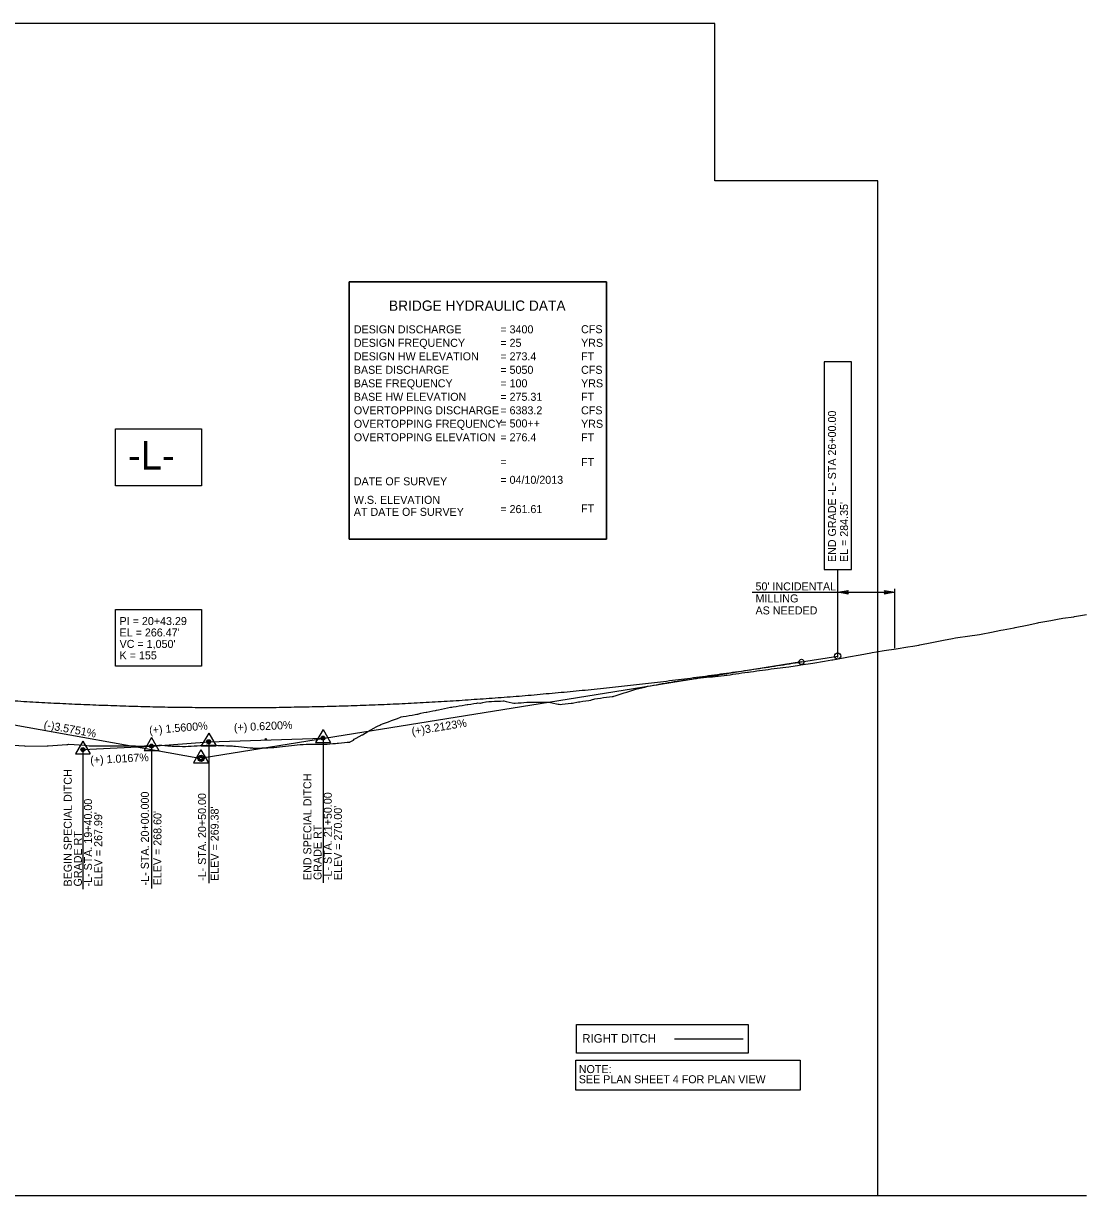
# Model space of a CAD drawing. Extents: x 10000 to 11818, y 10000 to 11025.
# Drawn here: x 10888 to 11818, y 10000 to 11025 of the extents above; entities that cross this region are included whole.
import ezdxf

# ---------------------------------------------------------------- set-up
doc = ezdxf.new("R2010")
doc.units = 0
for name, color, linetype in [('Exist Profile Cell', 7, 'Continuous'), ('Exist Vertical Profile Ground Line', 7, 'Continuous'), ('Prop Dimension', 7, 'Continuous'), ('Prop Grid Mask', 7, 'Continuous'), ('Prop PFL Ditch Label CELL', 7, 'Continuous'), ('Prop PFL VPI Symbol CELL', 7, 'Continuous'), ('Prop Plan Preparation Sheet Bridge Report Limited Study CELL', 7, 'Continuous'), ('Prop Terminator CELL', 7, 'Continuous'), ('Prop Vertical Profile Curve Label', 7, 'Continuous'), ('Prop Vertical Profile Ditch Grade Right', 7, 'Continuous'), ('Prop Vertical Profile Grade', 7, 'Continuous'), ('Prop Vertical Profile Grade Label', 7, 'Continuous'), ('Prop VPI Label', 7, 'Continuous'), ('Sheet Layout Profile Border', 7, 'Continuous'), ('Sheet Plot Border Outside CELL', 7, 'Continuous')]:
    doc.layers.add(name, color=color, linetype=linetype)

msp = doc.modelspace()

# ---------------------------------------------------------------- linework, layer by layer
at = {"layer": 'Exist Profile Cell'}
msp.add_line((10000, 10000), (11817.5, 10000), dxfattribs=at)
at = {"layer": 'Exist Vertical Profile Ground Line'}
msp.add_lwpolyline([(10869.3, 10394.5), (10889, 10393.2), (10889.9, 10393.1), (10908.7, 10393.2), (10909.6, 10393.2), (10926.1, 10394.3), (10926.5, 10394.4), (10926.9, 10394.5), (10927.6, 10394.8), (10941.4, 10393.9), (10945.4, 10393.2), (10967.1, 10393.4), (10968.6, 10393.4), (10970.5, 10393.4), (10978.2, 10393.3), (10980.8, 10393.2), (10983.3, 10393.2), (10985.9, 10393.2), (10988.8, 10393.1), (10991.1, 10393.1), (10993.8, 10393.2), (10996.2, 10393.3), (10998.8, 10393.4), (11001.4, 10393.5), (11003.9, 10393.6), (11006.5, 10393.8), (11009.1, 10393.9), (11011.7, 10393.6), (11014.2, 10393.4), (11016.8, 10393.2), (11018, 10393.1), (11019.4, 10393), (11022, 10393), (11024.5, 10392.9), (11027.1, 10392.8), (11029.3, 10392.7), (11029.7, 10392.7), (11032.2, 10392.9), (11034.8, 10393), (11037.4, 10393.2), (11040, 10393.3), (11042.5, 10393.5), (11043.2, 10393.5), (11045.1, 10393.6), (11047.7, 10393.8), (11049.7, 10393.9), (11050.3, 10393.9), (11052.8, 10393.9), (11053.9, 10393.9), (11055.4, 10393.8), (11058, 10393.7), (11060.6, 10393.6), (11063.1, 10393.5), (11065.7, 10393.4), (11068.3, 10393.3), (11070.5, 10393.2), (11070.9, 10393.2), (11072.1, 10393), (11073.4, 10392.9), (11076, 10392.6), (11078.6, 10392.4), (11081.1, 10392.1), (11083.7, 10391.8), (11086.3, 10391.6), (11088.3, 10391.4), (11088.9, 10391.3), (11090.6, 10391.1), (11091.4, 10391.2), (11092.6, 10391.3), (11094, 10391.3), (11096.6, 10391.4), (11099.2, 10391.5), (11101.7, 10391.6), (11104.3, 10391.7), (11105.4, 10391.8), (11106.9, 10391.9), (11109.5, 10392.1), (11111.7, 10392.3), (11112, 10392.3), (11114.6, 10392.6), (11117.2, 10392.9), (11119.8, 10393.2), (11122.3, 10393.5), (11124.9, 10393.8), (11127.5, 10394.1), (11130, 10394.3), (11132.6, 10394.5), (11135.2, 10394.6), (11137.8, 10394.6), (11140.3, 10394.7), (11142.9, 10394.7), (11143.8, 10394.8), (11145.5, 10394.7), (11148.1, 10394.7), (11150.6, 10394.7), (11153.2, 10394.7), (11153.7, 10394.7), (11155.8, 10394.9), (11158.4, 10395.2), (11160.9, 10395.4), (11162.2, 10395.5), (11163.5, 10395.7), (11166.1, 10395.9), (11168.7, 10396.2), (11171.2, 10396.4), (11173.3, 10396.6), (11173.8, 10396.9), (11176.6, 10398.3), (11177.2, 10399), (11178.9, 10400), (11181.5, 10401.4), (11184.1, 10402.8), (11184.5, 10403), (11186.7, 10404.3), (11189.2, 10405.7), (11191.8, 10407.2), (11194.4, 10408.6), (11196.5, 10409.8), (11197, 10410.1), (11197.6, 10410.5), (11199.5, 10411.4), (11200.6, 10411.8), (11202.1, 10412.4), (11204.7, 10413.4), (11207.3, 10414.4), (11209.8, 10415.4), (11212.4, 10416.3), (11215, 10417.3), (11217.6, 10418.3), (11218.2, 10418.6), (11220.1, 10418.9), (11222.7, 10419.3), (11225.3, 10419.8), (11227.8, 10420.2), (11230.4, 10420.7), (11232.1, 10420.9), (11233, 10421.1), (11235.6, 10421.7), (11238.1, 10422.3), (11240.2, 10422.7), (11240.7, 10422.8), (11243.3, 10423.3), (11245.9, 10423.8), (11248.4, 10424.3), (11249.3, 10424.5), (11251, 10424.8), (11253.6, 10425.4), (11256.2, 10425.9), (11258.7, 10426.4), (11261.3, 10427), (11262.5, 10427.2), (11263.9, 10427.4), (11266.5, 10427.8), (11269, 10428.2), (11271.6, 10428.6), (11274.2, 10429), (11276.1, 10429.3), (11276.7, 10429.4), (11279.3, 10429.8), (11281.9, 10430.3), (11284.5, 10430.7), (11285.1, 10430.8), (11287, 10430.7), (11287.7, 10430.7), (11289.6, 10431.1), (11292.2, 10431.7), (11292.7, 10431.9), (11294.8, 10432), (11297.3, 10432.1), (11299.9, 10432.2), (11302.5, 10432.3), (11305.1, 10432.4), (11307.6, 10432.5), (11308, 10432.5), (11310.2, 10432), (11312.8, 10431.5), (11315.4, 10430.9), (11316.7, 10430.6), (11317.9, 10430.7), (11320.5, 10430.9), (11323.1, 10431), (11325.6, 10431.2), (11328.2, 10431.4), (11331.1, 10431.6), (11331.4, 10431.6), (11332.4, 10431.6), (11333.4, 10431.6), (11335.9, 10431.6), (11338.5, 10431.6), (11341.1, 10431.5), (11343.7, 10431.5), (11346.2, 10431.5), (11346.8, 10431.5), (11348.8, 10431.1), (11351.4, 10430.6), (11354, 10430.1), (11355.7, 10429.8), (11356.5, 10429.7), (11357.9, 10429.4), (11359.1, 10429.6), (11361.7, 10429.9), (11364.3, 10430.2), (11366.8, 10430.5), (11368, 10430.7), (11369.4, 10430.9), (11372, 10431.4), (11373.3, 10431.7), (11374.5, 10431.8), (11377.1, 10432.2), (11379.7, 10432.5), (11382.3, 10432.8), (11384, 10433.1), (11384.8, 10433.4), (11387.7, 10434.4), (11390, 10434.7), (11392.6, 10435.1), (11395.1, 10435.4), (11397.7, 10435.7), (11400.3, 10436), (11402.9, 10436.3), (11403.6, 10436.4), (11404.3, 10436.6), (11405.4, 10437), (11408, 10437.9), (11410.6, 10438.7), (11413.2, 10439.5), (11415.7, 10440.3), (11418.3, 10441.1), (11420.9, 10441.9), (11423.4, 10442.8), (11426.1, 10443.5), (11428.6, 10444), (11430, 10444.2), (11431.2, 10444.6), (11433.2, 10445.3), (11433.7, 10445.4), (11436.3, 10445.8), (11438.9, 10446.2), (11441.5, 10446.6), (11442.1, 10446.7), (11444, 10447.2), (11446.5, 10447.8), (11449.2, 10448.2), (11451.8, 10448.6), (11454.3, 10449), (11456.9, 10449.4), (11459.5, 10449.8), (11461.2, 10450), (11462.1, 10450.2), (11464.6, 10450.6), (11467.2, 10450.9), (11469.8, 10451.3), (11472.3, 10451.7), (11474.9, 10452.1), (11476.6, 10452.3), (11477.5, 10452.4), (11480.1, 10452.7), (11482.6, 10453), (11485.2, 10453.2), (11487.8, 10453.5), (11490.4, 10453.7), (11492.9, 10454), (11494.1, 10454.1), (11495.5, 10454.3), (11498.1, 10454.6), (11500.7, 10454.8), (11502.2, 10455), (11503.2, 10455.2), (11505.8, 10455.5), (11508.4, 10455.9), (11511, 10456.3), (11513.5, 10456.6), (11516.1, 10457), (11518.7, 10457.4), (11521.2, 10457.7), (11522.1, 10457.8), (11523.8, 10458.1), (11526.4, 10458.4), (11529.2, 10458.8), (11531.5, 10459.1), (11534.1, 10459.5), (11536.7, 10459.8), (11539.3, 10460.1), (11541.8, 10460.5), (11544.4, 10460.8), (11547, 10461.1), (11549.6, 10461.5), (11552.1, 10461.8), (11554.7, 10462.1), (11557.3, 10462.5), (11559.1, 10462.7), (11564.9, 10463.6), (11567.7, 10464), (11578.1, 10465.7), (11588.5, 10467.3), (11594.9, 10468.4), (11595.6, 10468.5), (11598.9, 10469.1), (11609.3, 10471.1), (11619.7, 10473), (11628.9, 10474.7), (11630.1, 10474.9), (11633.8, 10475.6), (11640.6, 10476.6), (11651, 10478.2), (11661.4, 10479.8), (11665.7, 10480.5), (11670.8, 10481.3), (11671.8, 10481.5), (11682.2, 10483.5), (11692.6, 10485.6), (11700.2, 10487.1), (11703, 10487.6), (11704.9, 10488), (11713.4, 10489.2), (11723.8, 10490.7), (11725.4, 10490.9), (11734.3, 10492.6), (11742.6, 10494.3), (11744.7, 10494.7), (11754.3, 10496.6), (11755.1, 10496.8), (11765.5, 10498.9), (11774.9, 10500.8), (11775.9, 10501), (11786.3, 10503), (11792, 10504.1), (11796.7, 10504.8), (11806.3, 10506.2), (11807.1, 10506.4), (11817.5, 10508.2)], dxfattribs=at)
at = {"layer": 'Prop Dimension'}
msp.add_lwpolyline([(11172.7, 10573.9), (11397.7, 10573.9), (11397.7, 10798.9), (11172.7, 10798.9)], close=True, dxfattribs=at)
at = {"layer": 'Prop Grid Mask'}
for points in [[(11172.7, 10798.9), (11397.7, 10798.9), (11397.7, 10573.9), (11172.7, 10573.9)], [(11588.1, 10547.5), (11611.9, 10547.5), (11611.9, 10729), (11588.1, 10729)], [(10968.6, 10670.4), (11043.7, 10670.4), (11043.7, 10620.7), (10968.6, 10620.7)], [(10968.6, 10512.6), (11043.7, 10512.6), (11043.7, 10462.9), (10968.6, 10462.9)], [(11371.6, 10149.6), (11521.6, 10149.6), (11521.6, 10124.6), (11371.6, 10124.6)], [(11371, 10118.4), (11567, 10118.4), (11567, 10092.3), (11371, 10092.3)]]:
    msp.add_lwpolyline(points, close=True, dxfattribs=at)
at = {"layer": 'Prop PFL Ditch Label CELL'}
for p, q in [((11371.6, 10134.6), (11371.6, 10134.6)), ((11457.2, 10137), (11517.2, 10137))]:
    msp.add_line(p, q, dxfattribs=at)
at = {"layer": 'Prop PFL VPI Symbol CELL'}
for p, q in [((11050, 10404.4), (11043.5, 10393.2)), ((11050, 10404.4), (11056.5, 10393.2)), ((11150, 10407.5), (11143.5, 10396.3)), ((11150, 10407.5), (11156.5, 10396.3)), ((10940, 10397.4), (10933.5, 10386.2)), ((10940, 10397.4), (10946.5, 10386.2)), ((11000, 10400.5), (10993.5, 10389.3)), ((11000, 10400.5), (11006.5, 10389.3)), ((11143.5, 10396.3), (11156.5, 10396.3)), ((10933.5, 10386.2), (10946.5, 10386.2)), ((10993.5, 10389.3), (11006.5, 10389.3)), ((11043.2, 10389.7), (11036.8, 10378.5)), ((11043.2, 10389.7), (11049.7, 10378.5)), ((11043.5, 10393.2), (11056.5, 10393.2)), ((11036.8, 10378.5), (11049.7, 10378.5))]:
    msp.add_line(p, q, dxfattribs=at)
for centre, radius in [((11000, 10393), 1.75), ((11000, 10393), 1.2), ((11050, 10396.9), 1.75), ((11050, 10396.9), 1.2), ((11150, 10400), 1.75), ((11150, 10400), 1.2), ((10940, 10390), 1.75), ((10940, 10390), 1.2), ((11043.2, 10382.2), 1.75), ((11043.2, 10382.2), 1.2)]:
    msp.add_circle(centre, radius, dxfattribs=at)
at = {"layer": 'Prop Plan Preparation Sheet Bridge Report Limited Study CELL'}
for centre in [(11000, 10393), (11050, 10396.9), (11100, 10399.2), (11150, 10400), (10940, 10390)]:
    msp.add_circle(centre, 0.5, dxfattribs=at)
at = {"layer": 'Prop Terminator CELL'}
for points in [[(11609, 10526), (11600, 10527.6), (11609.1, 10529.2), (11607.9, 10527.6)], [(11641, 10529.1), (11650, 10527.6), (11641, 10526), (11642.1, 10527.6)]]:
    msp.add_lwpolyline(points, close=True, dxfattribs=at)
at = {"layer": 'Prop Vertical Profile Curve Label'}
msp.add_circle((11568.3, 10466.7), 2.25, dxfattribs=at)
at = {"layer": 'Prop Vertical Profile Ditch Grade Right'}
msp.add_lwpolyline([(10940, 10390), (11000, 10393), (11050, 10396.9), (11150, 10400)], dxfattribs=at)
at = {"layer": 'Prop Vertical Profile Grade'}
msp.add_line((11568.3, 10466.7), (11600, 10471.8), dxfattribs=at)
msp.add_spline([(10518.3, 10476.2), (10539.3, 10472.5), (10560.3, 10469), (10581.3, 10465.6), (10602.3, 10462.3), (10623.3, 10459.2), (10644.3, 10456.2), (10665.3, 10453.4), (10686.3, 10450.7), (10707.3, 10448.2), (10728.3, 10445.8), (10749.3, 10443.5), (10770.3, 10441.4), (10791.3, 10439.4), (10812.3, 10437.6), (10833.3, 10435.9), (10854.3, 10434.4), (10875.3, 10433), (10896.3, 10431.7), (10917.3, 10430.6), (10938.3, 10429.6), (10959.3, 10428.8), (10980.3, 10428.1), (11001.3, 10427.5), (11022.3, 10427.1), (11043.3, 10426.9), (11064.3, 10426.8), (11085.3, 10426.8), (11106.3, 10426.9), (11127.3, 10427.3), (11148.3, 10427.7), (11169.3, 10428.3), (11190.3, 10429), (11211.3, 10429.9), (11232.3, 10430.9), (11253.3, 10432.1), (11274.3, 10433.4), (11295.3, 10434.9), (11316.3, 10436.4), (11337.3, 10438.2), (11358.3, 10440.1), (11379.3, 10442.1), (11400.3, 10444.2), (11421.3, 10446.5), (11442.3, 10449), (11463.3, 10451.6), (11484.3, 10454.3), (11505.3, 10457.2), (11526.3, 10460.2), (11547.3, 10463.4), (11568.3, 10466.7)], degree=3, dxfattribs=at)
at = {"layer": 'Prop VPI Label'}
for p, q in [((11600, 10470.6), (11600, 10547.5)), ((11525.1, 10527.6), (11600, 10527.6)), ((11600, 10527.6), (11650, 10527.6)), ((11650, 10478.6), (11650, 10530.6)), ((10518.3, 10476.2), (11040.6, 10382.8)), ((11568.3, 10466.7), (11046, 10382.8))]:
    msp.add_line(p, q, dxfattribs=at)
for centre in [(11600, 10471.8), (11043.3, 10382.3)]:
    msp.add_circle(centre, 2.75, dxfattribs=at)
at = {"layer": 'Sheet Layout Profile Border'}
msp.add_lwpolyline([(10250, 11025), (10250, 10000), (10250, 10000), (11635, 10000), (11635, 10000), (11635, 10887.5), (11635, 10887.5), (11492.5, 10887.5), (11492.5, 11025)], close=True, dxfattribs=at)
at = {"layer": 'Sheet Plot Border Outside CELL'}
for p, q in [((11050, 10396.9), (11050, 10273.2)), ((11150, 10400), (11150, 10273.5)), ((10940, 10390), (10940, 10267.8)), ((11000, 10393), (11000, 10268.6))]:
    msp.add_line(p, q, dxfattribs=at)

# ---------------------------------------------------------------- texts
at = {"layer": 'Prop Dimension'}
for s, height, p in [('BRIDGE HYDRAULIC DATA', 9, (11207.6, 10773.7)), ('DESIGN DISCHARGE', 7, (11176.9, 10754)), ('= 3400    ', 7, (11305, 10754)), ('CFS', 7, (11375.6, 10754.1)), ('DESIGN FREQUENCY', 7, (11176.9, 10742.2)), ('= 25 ', 7, (11305, 10742.2)), ('YRS', 7, (11375.6, 10742.2)), ('DESIGN HW ELEVATION', 7, (11176.9, 10730.4)), ('= 273.4   ', 7, (11305, 10730.4)), ('FT', 7, (11375.6, 10730.4)), ('BASE DISCHARGE', 7, (11176.9, 10718.6)), ('= 5050    ', 7, (11305, 10718.6)), ('CFS', 7, (11375.6, 10718.6)), ('BASE FREQUENCY', 7, (11176.9, 10706.8)), ('= 100', 7, (11305, 10706.8)), ('YRS', 7, (11375.6, 10706.8)), ('BASE HW ELEVATION', 7, (11176.9, 10695)), ('= 275.31  ', 7, (11305, 10695)), ('FT', 7, (11375.6, 10695)), ('OVERTOPPING DISCHARGE', 7, (11176.9, 10683.2)), ('= 6383.2  ', 7, (11305, 10683.2)), ('CFS', 7, (11375.6, 10683.2)), ('OVERTOPPING FREQUENCY', 7, (11176.9, 10671.4)), ('= 500++', 7, (11305, 10671.7)), ('YRS', 7, (11375.6, 10671.4)), ('OVERTOPPING ELEVATION', 7, (11176.9, 10659.6)), ('= 276.4   ', 7, (11305, 10659.6)), ('FT', 7, (11375.6, 10659.6)), ('=         ', 7, (11305, 10638)), ('FT', 7, (11375.6, 10638)), ('= 04/10/2013', 7, (11305, 10622.4)), ('DATE OF SURVEY', 7, (11176.9, 10621.1)), ('W.S. ELEVATION', 7, (11176.9, 10604.9)), ('AT DATE OF SURVEY', 7, (11176.9, 10594.4)), ('= 261.61  ', 7, (11305, 10596.8)), ('FT', 7, (11375.6, 10597.4))]:
    msp.add_text(s, height=height, dxfattribs=at).set_placement(p)
at = {"layer": 'Prop PFL Ditch Label CELL'}
msp.add_text('RIGHT DITCH', height=7.485, dxfattribs=at).set_placement((11376.6, 10133.7))
at = {"layer": 'Prop Plan Preparation Sheet Bridge Report Limited Study CELL'}
for s, p in [('BEGIN SPECIAL DITCH', (10930.3, 10270.3)), ('END SPECIAL DITCH', (11139.8, 10275.9)), ('-L- STA. 20+00.000', (10997.7, 10271.3)), ('-L- STA. 19+40.00', (10948, 10270.3)), ('-L- STA. 20+50.00', (11047.7, 10275.2)), ('-L- STA. 21+50.00', (11157.6, 10275.9)), ("ELEV = 267.99'", (10956.9, 10270.3)), ("ELEV = 268.60'", (11008.7, 10271.3)), ("ELEV = 269.38'", (11058.7, 10275.2)), ("ELEV = 270.00'", (11166.5, 10275.9)), ('GRADE RT', (11148.7, 10275.9)), ('GRADE RT', (10939.1, 10270.3))]:
    msp.add_text(s, height=7, rotation=90, dxfattribs=at).set_placement(p)
at = {"layer": 'Prop Vertical Profile Curve Label'}
for s, p in [("VC = 1,050'", (10972.1, 10478.9)), ('K = 155', (10972.1, 10468.9))]:
    msp.add_text(s, height=7, dxfattribs=at).set_placement(p)
at = {"layer": 'Prop Vertical Profile Grade Label'}
for s, rotation, p in [('(-)3.5751%', 349.8652, (10905.4, 10408.6)), ('(+)3.2123%', 9.1246, (11228, 10402.4))]:
    msp.add_text(s, height=7, rotation=rotation, dxfattribs=at).set_placement(p)
at = {"layer": 'Prop VPI Label'}
for s, rotation, p in [('END GRADE -L- STA 26+00.00', 90, (11598.5, 10554)), ("EL = 284.35'", 90, (11609, 10554)), ("50' INCIDENTAL", 360, (11528.1, 10529.2)), ('MILLING', 360, (11528.1, 10518.7)), ('AS NEEDED', 360, (11528.1, 10508.2))]:
    msp.add_text(s, height=7, rotation=rotation, dxfattribs=at).set_placement(p)
for s, height, p in [('-L-', 25, (10979.5, 10634.9)), ('PI = 20+43.29', 7, (10972.1, 10498.9)), ("EL = 266.47'", 7, (10972.1, 10488.9)), ('NOTE:', 7, (11373.6, 10107.1)), ('SEE PLAN SHEET 4 FOR PLAN VIEW', 7, (11373.6, 10098.2))]:
    msp.add_text(s, height=height, dxfattribs=at).set_placement(p)
at = {"layer": 'Sheet Plot Border Outside CELL'}
for s, rotation, p in [('(+) 1.5600%', 4.46, (10998.2, 10403.5)), ('(+) 0.6200%', 2.6909, (11072.2, 10405.8)), ('(+) 1.0167%', 2.91, (10946.6, 10377.3))]:
    msp.add_text(s, height=7, rotation=rotation, dxfattribs=at).set_placement(p)

doc.saveas('drawing.dxf')
